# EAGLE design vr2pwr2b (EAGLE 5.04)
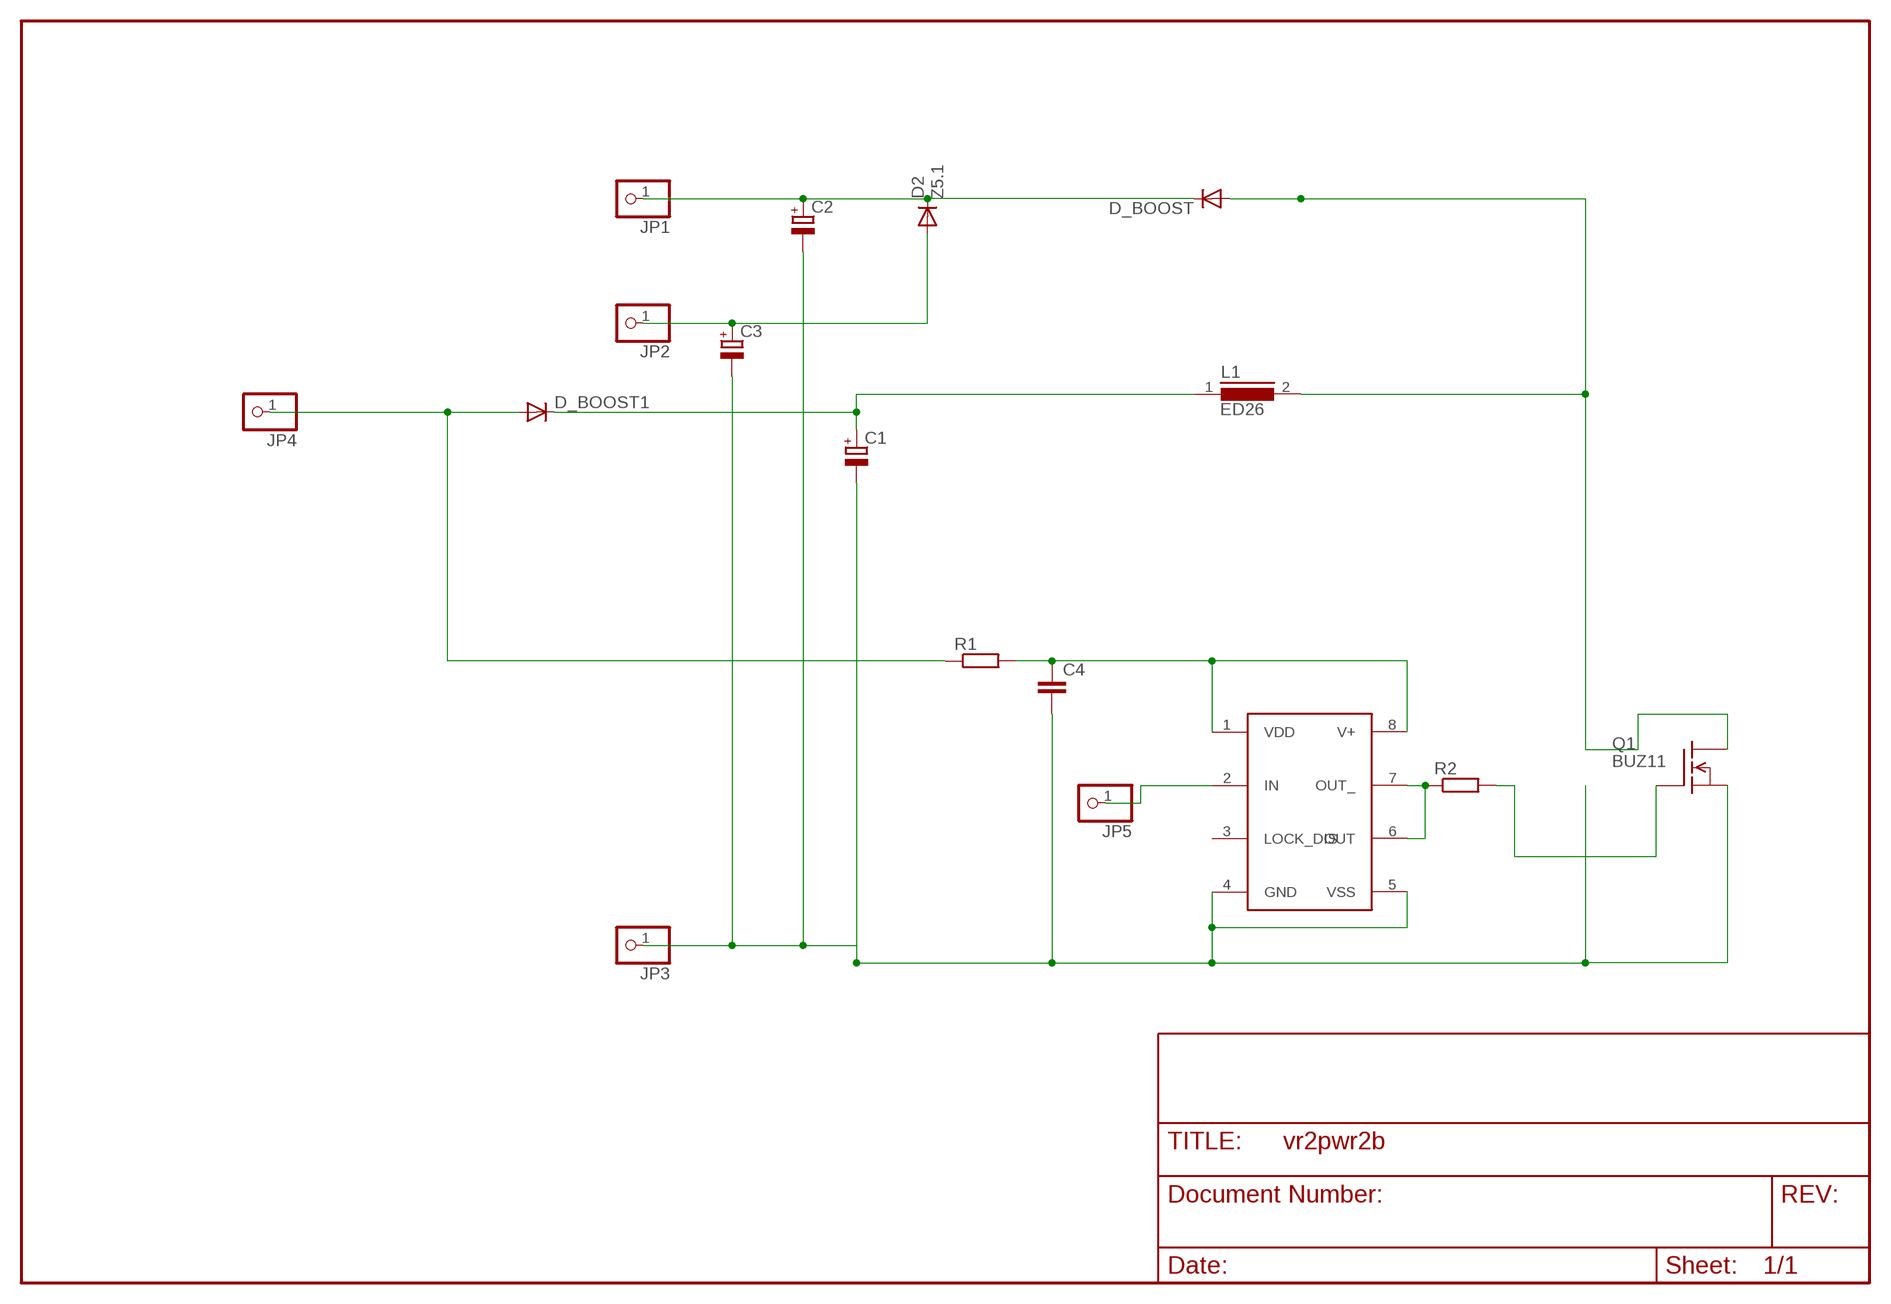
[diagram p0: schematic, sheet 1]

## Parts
C1  CPOL-EUE2.5-7  [E2,5-7]
C2  CPOL-EUE2.5-7  [E2,5-7]
C3  CPOL-EUE2-4  [E2-4]
C4  C-EUC0805  [C0805]
D2  Z5.1  DIODE-D-2.5  [D-2.5]
D_BOOST  DIODE-D-10  [D-10]
D_BOOST1  DIODE-D-10  [D-10]
IC1  TC4432X  [SO-08]
JP1  PINHD-1X1  [1X01]
JP2  PINHD-1X1  [1X01]
JP3  PINHD-1X1  [1X01]
JP4  PINHD-1X1  [1X01]
JP5  PINHD-1X1  [1X01]
L1  ED26  [ED26]
Q1  BUZ11  [TO220V]
R1  R-EU_0207/15  [0207/15]
R2  R-EU_R1206  [R1206]

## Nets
GND: C1.- C2.- C3.- C4.2 IC1.4(GND) IC1.5(VSS) JP3.1 Q1.3(S)
HOTSPOT: D_BOOST.A L1.2 Q1.2(D)
LOAD: C2.+ D2.C D_BOOST.C JP1.1
N$1: IC1.2(IN) JP5.1
N$2: C1.+ D_BOOST1.C L1.1
N$3: IC1.6(OUT) IC1.7(OUT_) R2.1
N$4: C3.+ D2.A JP2.1
N$5: D_BOOST1.A JP4.1 R1.1
N$6: Q1.1(G) R2.2
N$7: C4.1 IC1.1(VDD) IC1.8(V+) R1.2
Unconnected: IC1.3(LOCK_DIS)

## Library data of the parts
C1-C3 = rcl(2):CPOL-EU: POLARIZED CAPACITOR, European symbol
C4 = rcl-2:C-EU: CAPACITOR, European symbol
D2 D_BOOST D_BOOST1 = diode:DIODE-: DIODE
IC1 = microchip:TC4432
JP1-JP5 = pinhead:PINHD-1X1: PIN HEADER
L1 = inductors:ED26: INDUCTOR
Q1 = transistor-fet:BUZ11: N-Channel Enhancement MOSFET 50V; 30A; 0,040Ohm
R1 R2 = rcl-2:R-EU_: RESISTOR, European symbol

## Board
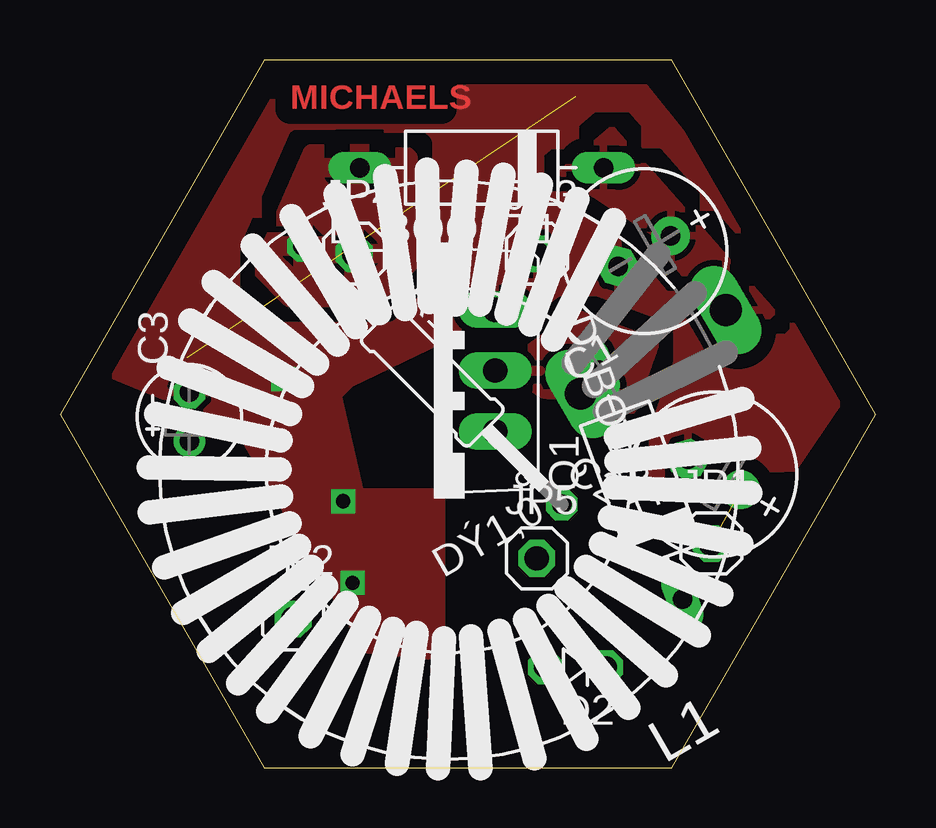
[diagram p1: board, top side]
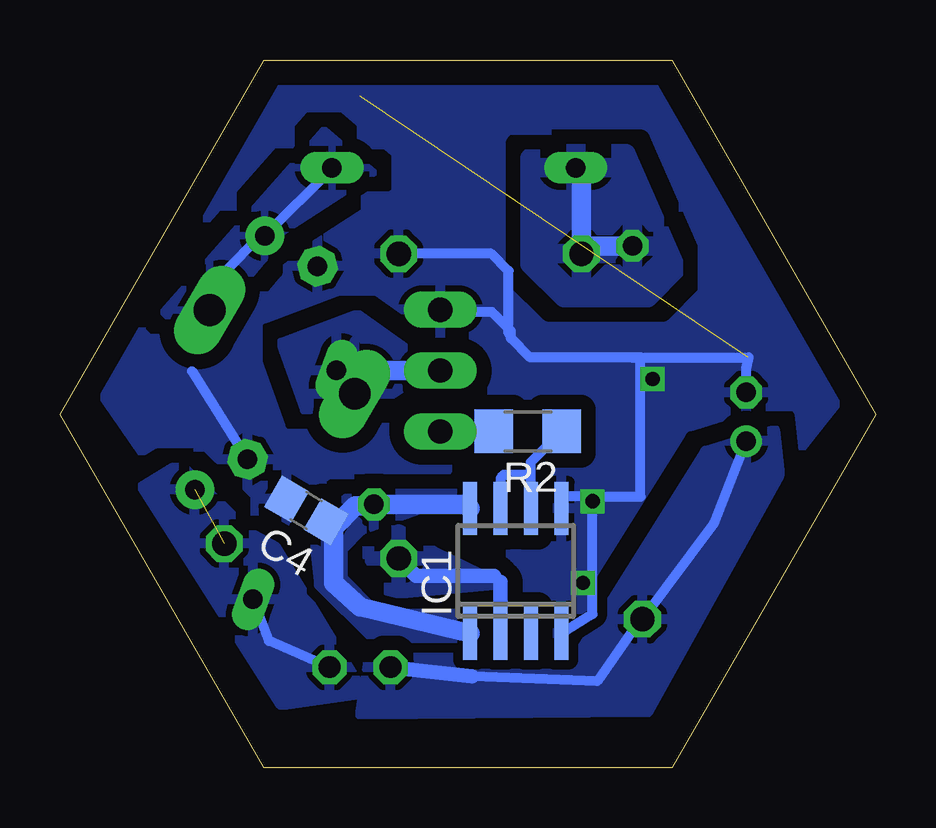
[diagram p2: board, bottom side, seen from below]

Size 34 x 29.5 mm. Coordinates in mm from the lower left corner, seen from the top.
Outline: 8.5,0 25.5,0 34,14.72 25.5,29.5 8.5,29.5 0,14.72 8.5,0
Copper layers (1*16): Top 0.035mm / dielectric 1.5mm / Bottom 0.035mm
Design rules "default": minimum track width 10mil, minimum drill 24mil, track to track 8mil, track to pad 8mil, pad to pad 8mil, via to via 8mil, smd to smd 8mil, copper to edge 40mil, drill to drill 8mil, minimum pad ring 10mil, minimum via ring 8mil, stop-mask expansion 4mil, vias tented up to drill 0mil, thermal gap 10mil

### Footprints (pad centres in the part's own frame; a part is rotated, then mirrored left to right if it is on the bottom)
E2,5-7 = drill 0.813 pad 1.6 round: + -1.27,0 | drill 0.813 pad 1.6 octagon: - 1.27,0
E2-4 = drill 0.813 pad 1.27 round: + -1.016,0 | drill 0.813 pad 1.27 octagon: - 1.016,0
C0805 = smd 1.3 x 1.5: 1 -0.95,0; 2 0.95,0
D-2.5 = drill 0.9 octagon: A 1.27,0; C -1.27,0
D-10 = drill 0.813 long: A 5.08,0; C -5.08,0
SO-08 = smd 0.6 x 2.2: 1 -1.905,-2.6; 2 -0.635,-2.6; 3 0.635,-2.6; 4 1.905,-2.6; 5 1.905,2.6; 6 0.635,2.6; 7 -0.635,2.6; 8 -1.905,2.6
1X01 = drill 1.016 octagon: 1 0,0
ED26 = drill 1.321 long: 1 -13.335,0; 2 -6.35,0
TO220V = drill 1.016 long: 1 -2.54,-2.54; 2 0,-2.54; 3 2.54,-2.54
0207/15 = drill 0.813 octagon: 1 -7.62,0; 2 7.62,0
R1206 = smd 1.6 x 1.803: 1 -1.422,0; 2 1.422,0

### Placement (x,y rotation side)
C1  24.36,21.53 210 top
C2  27.28,12.22 150 top
C3  5.39,14.62 90 top
C4  23.72,10.72 150 bottom
D2  21.49,4.18 180 top
D_BOOST  24.21,11.79 110 top
D_BOOST1  17.58,25.01 180 top
IC1  15,8.2 0 bottom
JP1  27.15,9.34 0 top
JP2  9.72,6.18 0 top
JP3  19.88,21.42 0 top
JP4  12.26,21.42 0 top
JP5  19.88,8.72 0 top
L1  16.21,12.4 210 top
Q1  15.6,16.55 90 top
R1  15.52,16.36 315 top
R2  14.5,14.02 180 bottom

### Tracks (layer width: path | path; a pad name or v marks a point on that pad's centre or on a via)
GND  (via drill 0.6)  (1 unrouted)
  Bottom 0.406: IC1.4 11.8,6.4 v11.8,11.1 11.8,11.3 | 11.8,11.3 12.99,11.3 IC1.5 | 11.8,11.3 9.8,11.3 9.8,17.1 10.2,17.1 | C2.- 28.5,16.53 | 10.2,17.1 5.3,17.1 5.4,16.64 C3.- | 10.2,17.1 14.4,17.1 15.2,17.9 15.2,18 | 15.2,18 15.2,18.2 16,19 17.81,19 | JP3.1 16.02,21.42 15.3,20.7 15.3,18.1 15.2,18
  other vias: 12.2,7.7 9.3,16.2
  pour Bottom (isolate 0.61, rank 3): 0.9,16.1 8,29.7 26.5,29.9 32.7,16.2 24.8,4.8 9.9,4.7
  pour Top (isolate 0.61, rank 3): 23.8,29.1 33.6,16.9 30.6,12.5 24.7,12.2 24.7,18.4 17.5,18.6 12.1,16 11.6,15.5 12.5,11.5 15.9,11.5 15.9,4.6 12.8,4.9 7.4,14.2 1.1,16.8 8.7,29.2
HOTSPOT
  Bottom 0.406: L1.2 D_BOOST.A
  Bottom 0.813: Q1.2 20.74,16.55 L1.2
  pour Bottom: 18.5,16.7 21.6,18.9 24.8,17.7 23.8,14.9 20.1,15.6
  pour Top: 18.5,16.7 21.6,18.9 24.8,17.7 23.8,14.9 20.1,15.6
LOAD  (1 unrouted)
  Bottom 0.406: D2.C 25.28,5.28 D_BOOST.C
  pour Bottom (isolate 0.305, rank 2): 24.8,2.6 21.3,3.1 25,9.2 26.1,9.8 28.8,12.5 29.3,12.5 30.6,11.7
N$1
  Bottom 0.406: 15.63,7.74 15.9,8
  Bottom 0.61: IC1.2 15.63,7.74 | 15.9,8 19.16,8 JP5.1
  pour Bottom (isolate 0.305): 18.4,8.9 20.1,10 21.2,9 20.2,7.3 15.9,7.7
N$2
  Bottom 0.406: D_BOOST1.C 22.66,24.97 C1.+ 25.63,22.17 27.2,20.6 27.2,19.64 L1.1
  pour Bottom (isolate 0.305): 23,26.6 29.7,19 28.4,17.7 25.5,21.2 25.1,22.1 20.9,24.8
  pour Top (isolate 0.305): 23,26.6 29.7,19 28.4,17.7 25.5,21.2 25.1,22.1 20.9,24.8
N$3
  Bottom 0.406: IC1.6 14.37,12.2 | 14.37,12.2 14.37,12.73 R2.1 | IC1.7 15.63,12.06 15.5,12.2 14.37,12.2
N$4
  Bottom 0.406: C3.+ 6.72,10.21 JP2.1 9.8,6.18 11.6,3.6 16.82,3.8
  Bottom 0.61: 16.82,3.8 D2.A
  pour Bottom (isolate 0.406, rank 2): 4.2,14.1 4,12.2 9.5,2.3 21.5,2.2 21.1,4.7 12.5,4.6 7.1,13.2
N$5
  Bottom 0.813: R1.1 11.93,21.75 JP4.1 12.26,24.77 D_BOOST1.A
  pour Bottom (isolate 0.305): 10.4,25.6 14.2,25.6 14.4,25.4 14.4,21 13,19.6 9.5,19.6 8.3,20.8
  pour Top (isolate 0.305): 10.5,25.6 14.3,25.6 14.5,25.4 14.5,21 13.1,19.6 9.6,19.6 8.4,20.8
N$6
  Bottom 0.813: Q1.1 15.93,14.01 R2.2
N$7
  Bottom 0.813: IC1.1 21.5,6.7 22.6,7.7 22.6,9.94 | 22.6,9.94 C4.1 | 22.6,9.94 22.6,10 21.7,10.9 20.98,10.9 R1.2 17.07,10.97 IC1.8
  pour Bottom (isolate 0.61): 17.2,11.4 21.8,11.4 23.5,10.2 23.2,7.6 21,5.4 16.8,5.4 16.8,5.9 17.3,6.4 20.8,6.4 20.9,6.5 20.9,6.6 22.2,7.9 22.2,9.1 21.4,9.9

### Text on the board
Top: MICHAELS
